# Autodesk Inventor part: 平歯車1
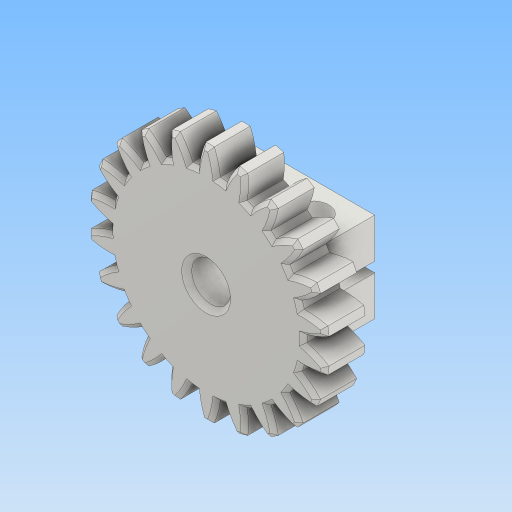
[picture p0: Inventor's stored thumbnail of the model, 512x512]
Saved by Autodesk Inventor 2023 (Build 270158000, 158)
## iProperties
CustomPartVersion: 1
Created: 2024-01
Part Number: 平歯車1
Material: Steel
Document SubType Name: Modeling
Designer: kumagai
Categories: <?xml version="1.0" encoding="UTF-16"?> <MemberInstance><Categories><FamilyTemplate><FamilyTemplateParameter ValueType="xs:double" Id="1" ObjectReferenceKey="da
Density: 1 g/cm^3
Appearance: Steel
Author: kumagai
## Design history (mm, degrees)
sketch "Sketch1"
  geometry: C1 r 12 at (0, 0); C2 r 1.95 at (0, 0); 1 further point
  constraints: 2 centre point, 2 coincident
  dimensions: "d0" = 24 diameter of C1 (= da_da); "d49" = 3.9 diameter of C2
extrude "Extrusion1" new body sketch "Sketch1" distance "d1" = 4 (= da_b); taper "d2" = 0 deg
workplane "Work Plane2"
sketch "Sketch2"
  geometry: C1 r 12 at (0, 0) reference; C2 r 11 at (0, 0)
  constraints: 1 centre point, 1 coincident
  dimensions: "d3" = 22 diameter of C2 (= da_d)
feature "ピッチ円直径" sketch "Sketch2" dims "d4" = 10, "d5" = 0
workplane "Work Plane8"
workplane "Work Plane9"
feature "平歯車" dims "da_b" = 4, "da_d" = 22, "da_aw" = 22, "da_da" = 24, "da_df" = 19.5, "da_dw" = 22, angle "da_beta" = 0 deg, "da_lefttooth" = 0, "da_righttooth" = 0
sketch "スケッチ3"
  geometry: L1 (0, 3.24)-(0, -5.79) reference; L2 (-9.66, 0)-(9.66, 0) reference; L3 (-6.9, -0.5)-(6.9, -0.5); L4 (6.9, -0.5)-(6.9, -4.5); L5 (6.9, -4.5)-(-6.9, -4.5); L6 (-6.9, -4.5)-(-6.9, -0.5); C1 r 1.95 at (0, 0); 3 further points
  constraints: 8 end point, 1 centre point, 1 coincident, 1 other
  dimensions: "d54" = 0.5 distance between parallel lines of L2 L3; "d55" = 6.9 distance between parallel lines of L6 L1; "d56" = 4.5 distance between parallel lines of L2 L5; "d59" = 3.9 diameter of C1
extrude "押し出し2" join sketch "スケッチ3" distance "d57" = 6; taper "d58" = 0 deg
sketch "スケッチ4"
  geometry: L1 (0, -5.52)-(0, 0.92) reference; L2 (-7.42, 0)-(7.42, 0) reference; C1 r 1.6 at (3.7, -3); C2 r 1.6 at (-3.7, -3); 1 further point
  constraints: 2 centre point, 1 other
  dimensions: "d60" = 3.2 diameter of C1; "d61" = 3 distance from line of L2 C1.centre; "d62" = 3.7 distance from line of L1 C1.centre
extrude "押し出し3" cut sketch "スケッチ4" extent not by distance; stored distance "d63" = 0; taper "d64" = 0 deg
pattern_circular "円形状パターン1" dims angle "d66" = 360 deg
chamfer "面取り2" distance "d68" = 0.5; stored, may be unused: second distance "d69" = 2, angle "d70" = 45 deg
chamfer "面取り3" distance "d81" = 0.4; stored, may be unused: second distance "d82" = 2, angle "d83" = 45 deg
body "Solid1"
body "Srf1"
other parameters: "d16" = 22 (= da_aw), "d17" = 0, "d34" = 1.428 (computed from da_z), "d39" = 0, "d41" = 0, "d43" = 22 (= da_aw), "d46" = 22 (= da_aw), "d47" = 0, "d48" = 0
